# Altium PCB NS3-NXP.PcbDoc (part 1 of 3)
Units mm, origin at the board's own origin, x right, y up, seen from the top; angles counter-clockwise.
Board outline 147 x 83 mm, 2 copper layers (Top Layer, Bottom Layer); 303 components, 312 nets, 1163 pads, 118 vias.
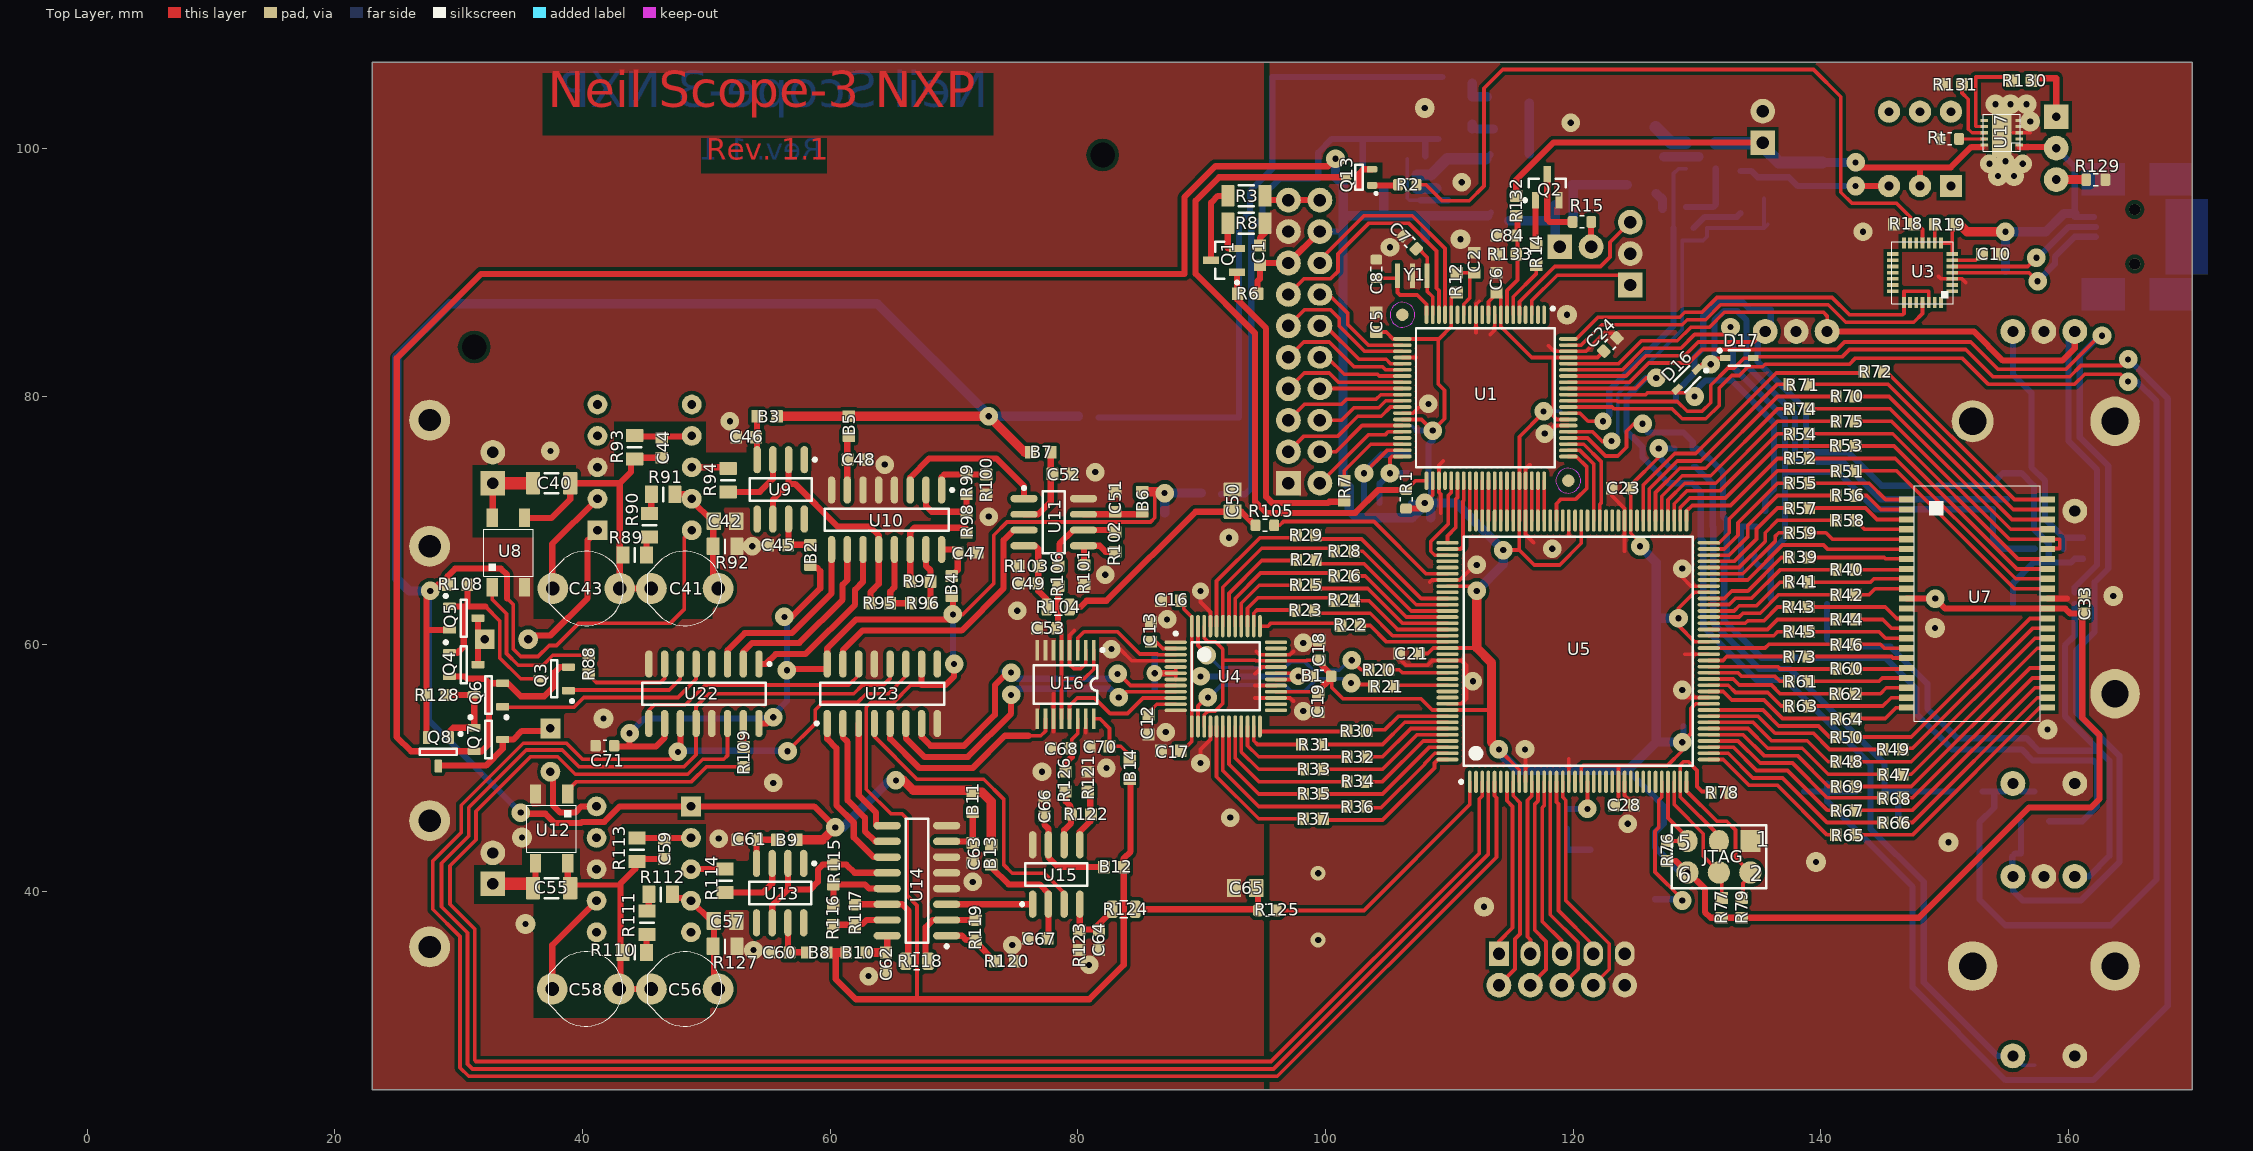
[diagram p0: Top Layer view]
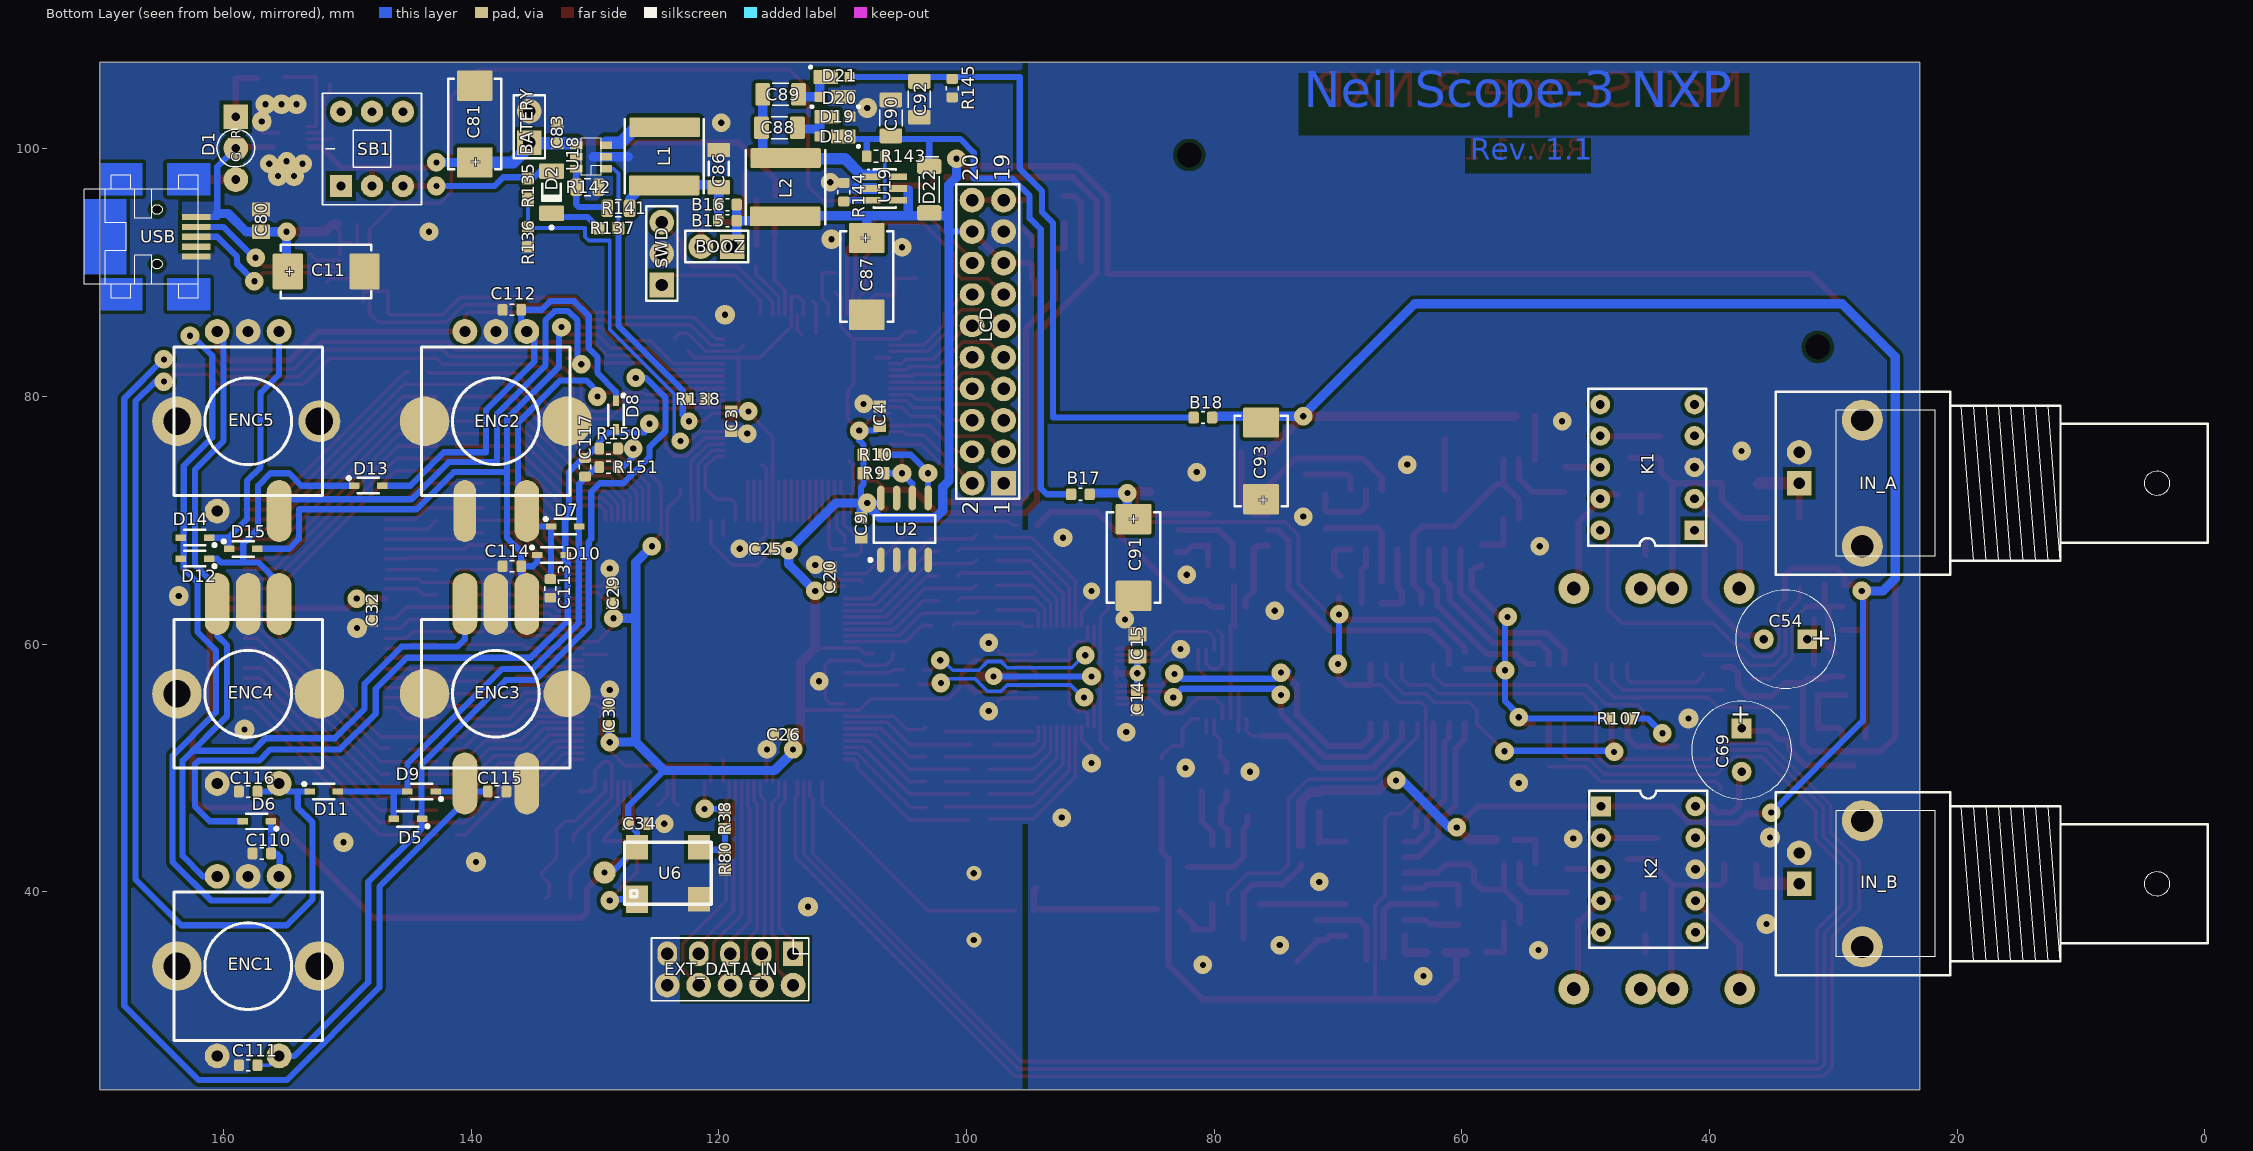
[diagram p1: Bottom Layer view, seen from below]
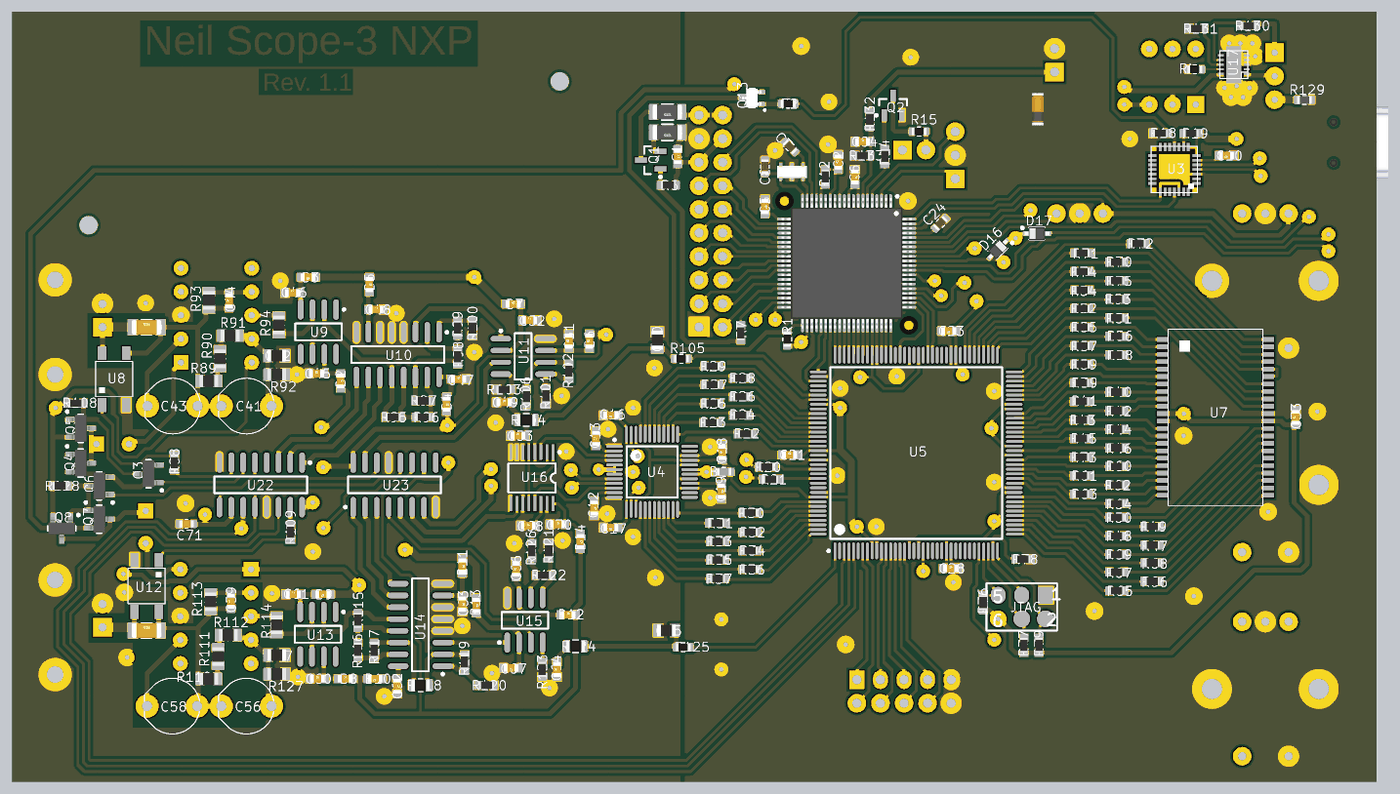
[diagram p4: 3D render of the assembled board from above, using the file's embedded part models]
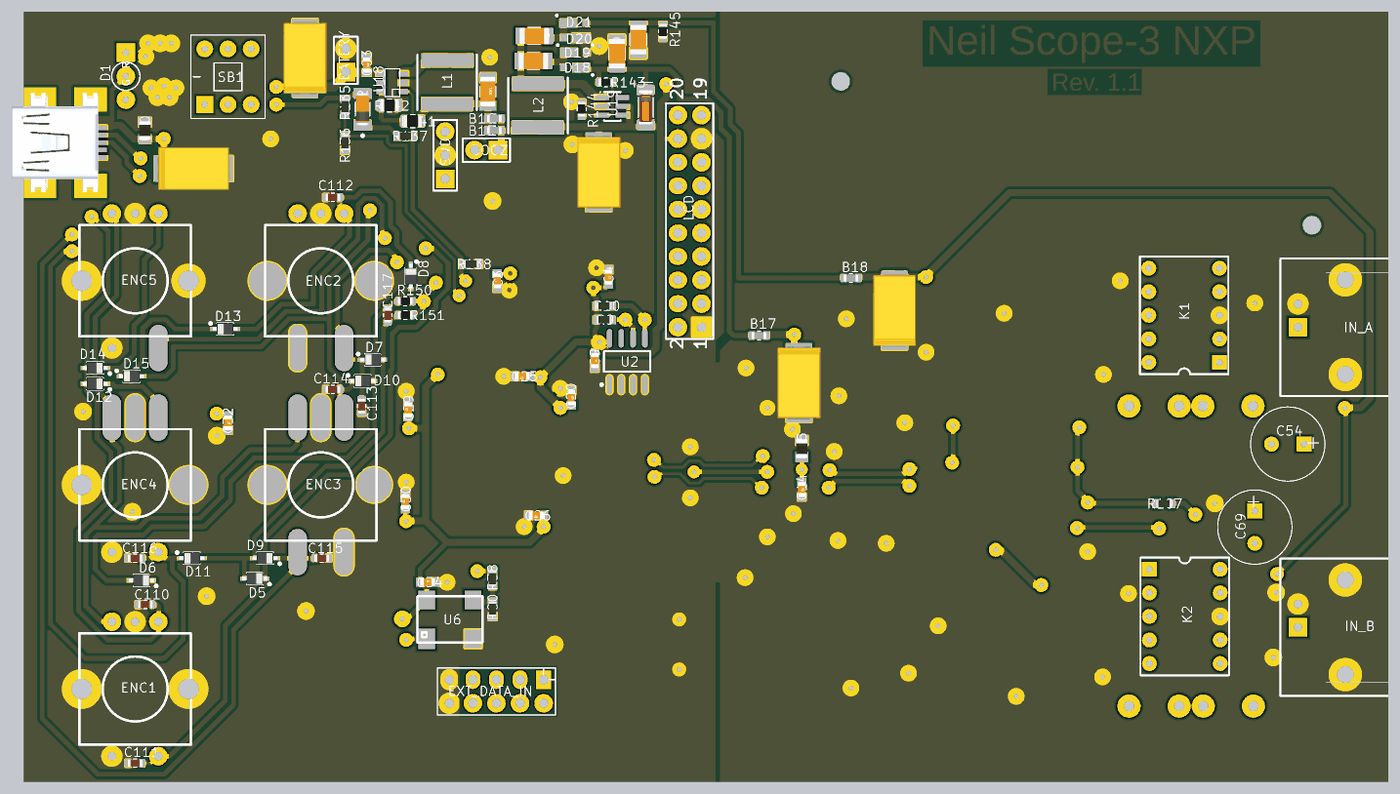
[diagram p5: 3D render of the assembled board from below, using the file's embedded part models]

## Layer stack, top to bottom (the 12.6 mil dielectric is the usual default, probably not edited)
Top Layer: signal copper 0.0356
Dielectric: dielectric 0.32, FR-4, Dk 4.8
Bottom Layer: signal copper 0.0356

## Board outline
23,24 170,24 170,107 23,107

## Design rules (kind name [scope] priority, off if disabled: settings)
Clearance Clearance_2 [InNet('AGND') vs InNet('DGND')] p1: gap=0
Clearance Clearance_1 [(IsPad OR IsTrack) vs (IsPad OR IsTrack)] p2: gap=0.19
Clearance [All] p3: gap=0.3
ComponentClearance [All] p1 off: gap=0.254 collisioncheckmode=3 verticalgap=0.254 showdistances=FALSE
MinimumSolderMaskSliver [All] p1 off: minsoldermaskwidth=0.254
PasteMaskExpansion [All] p1 off: expansion=0
PlaneClearance [All] p1: clearance=0.4
PlaneConnect [All] p1: planeconnectstyle=Relief reliefexpansion=0.508 reliefentries=4 reliefconductorwidth=0.4 reliefairgap=0.4
PolygonConnect [All] p1: connectstyle=Relief reliefconductorwidth=0.5 reliefentries=4 polygonreliefangle="90 Angle" airgapwidth=-0.1
RoutingVias [All] p1: holewidth=0.5 width=1.5 viastyle="Through Hole" minholewidth=0.5 minwidth=1 maxholewidth=0.6 maxwidth=2
ShortCircuit ShortCircuit_1 [InNet('AGND') vs InNet('DGND')] p1: allowed=TRUE
ShortCircuit [All] p2: allowed=FALSE
SilkToSilkClearance [All] p1 off: silktosilkclearance=0.254
SilkscreenOverComponentPads [IsPad] p1 off: minsilkscreentomaskgap=0.254
SolderMaskExpansion [All] p1 off: expansion=0.15
Width [All] p1: maxlimit=2 minlimit=0.25 preferedwidth=0.3
20 further rules are at their usual default settings.

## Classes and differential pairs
component class U_Analog: B2 B3 B4 B5 B6 B7 B8 B9 B10 B11 B12 B13 B14 C40 C41 C42 C43 C44 C45 C46 C47 C48 C49 C50 C51 C52 C53 C54 C55 C56 C57 C58 C59 C60 C61 C62 C63 C64 C65 C66 C67 C68 C69 C70 C71 IN_A IN_B K1 K2 Q3 Q4 Q5 Q6 Q7 Q8 R88 R89 R90 R91 R92 R93 R94 R95 R96 R97 R98 R99 R100 R101 R102 R103 R104 R105 R106 R107 R108 R109 R110 R111 R112 R113 R114 R115 R116 R117 R118 R119 R120 R121 R122 R123 R124 R125 R126 R127 R128 U8 U9 U10 U11 U12 U13 U14 U15 U16 U22 U23
net class ENCBUT[3..0]: ENCBUT0 ENCBUT1 ENCBUT2 ENCBUT3
net class ENCA[2..0]: ENCA0 ENCA1 ENCA2
net class Q[7..0]: Q0 Q1 Q2 Q3 Q4 Q5 Q6 Q7

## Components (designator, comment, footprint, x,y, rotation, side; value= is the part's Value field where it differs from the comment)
B1 "BEAD" BEAD0603 99.7,57.4 r0 top
B2 "BEAD" C0603NH080 58.4,67.2 r270 top
B3 "BEAD" C0603NH080 54.9,78.4 r180 top
B4 "BEAD" C0603NH080 69.8,64.7 r270 top
B5 "BEAD" C0603NH080 61.5,77.6 r270 top
B6 "BEAD" C0603NH080 85.2,71.5 r90 top
B7 "BEAD" C0603NH080 77,75.5 r0 top
B8 "BEAD" C0603NH080 58.9,35.1 r0 top
B9 "BEAD" C0603NH080 56.5,44.2 r180 top
B10 "BEAD" C0603NH080 62.1,35.1 r180 top
B11 "BEAD" C0603NH080 71.5,47.25 r270 top
B12 "BEAD" C0603NH080 82.9,42 r0 top
B13 "BEAD" C0603NH080 73,43 r270 top
B14 "BEAD" C0603NH080 84.2,49.9 r270 top
B15 "BEAD" BEAD0603 119.3,94.2 r180 bottom
B16 "BEAD" BEAD0603 119.3,95.5 r180 bottom
B17 "BEAD" BEAD0603 90.8,72.1 r180 bottom
B18 "BEAD" BEAD0603 80.9,78.3 r180 bottom
BATERY "Header 2" HDR1X2 135.3,100.5 r90 bottom
BOOZ "Header 2" HDR1X2 118.9,92.1 r0 bottom
C1 "Cap" C0603NH080 94.7,91.4 r270 top
C2 "Cap" C0603NH080 112,90.8 r90 top
C3 "Cap" C0603NH080 119,78 r90 bottom
C4 "Cap" C0603NH080 107,78.4 r270 bottom
C5 "Cap" C0603NH080 104.1,86 r270 top
C6 "Cap" C0603NH080 113.8,89.2 r270 top
C7 "Cap" C0603_Samsung 106.8,92.45 r315 top
C8 "Cap" C0603_Samsung 104.1,90.3 r270 top
C9 "Cap" C0603NH080 108.5,69.4 r270 bottom
C10 "Cap" C0603NH080 153.8,91.5 r180 top
C11 "ECap" CAPMP7343X280N 151.7,90.1 r180 bottom
C12 "Cap" C0603NH080 85.7,53.5 r270 top
C13 "Cap" C0603NH080 85.9,61 r90 top
C14 "Cap" C0603NH080 86.2,55.5 r270 bottom
C15 "Cap" C0805NH145 86.2,59.9 r270 bottom
C16 "Cap" C0603NH080 87.5,63.5 r180 top
C17 "Cap" C0603NH080 87.5,51.4 r180 top
C18 "Cap" C0603NH080 99.5,59.5 r90 top
C19 "Cap" C0603NH080 99.4,55.3 r270 top
C20 "Cap" C0603NH080 111,65.4 r270 bottom
C21 "Cap" C0603NH080 106.75,59.25 r0 top
C23 "Cap" C0603NH080 123.9,72.6 r180 top
C24 "Cap" C0603_Samsung 123,84.2 r45 top
C25 "Cap" C0603NH080 116.3,67.7 r0 bottom
C26 "Cap" C0603NH080 114.8,52.7 r0 bottom
C28 "Cap" C0603NH080 124.1,47 r0 top
C29 "Cap" C0603NH080 128.6,64.1 r90 bottom
C30 "Cap" C0603NH080 128.9,54.2 r90 bottom
C32 "Cap" C0603NH080 148,62.7 r270 bottom
C33 "Cap" C0603NH080 161.252,63.276 r90 top
C34 "Cap" C0603NH080 126.5,45.5 r180 bottom
C40 "Cap" C1206NH190 37.5,73 r0 top
C41 "Cap_Var" Cap_Var 48.25,64.5 r180 top
C42 "Cap" C0805NH145 51.501,69.926 r180 top
C43 "Cap_Var" Cap_Var 40.3,64.5 r180 top
C44 "NPO" C0603NH080 46.4,75.85 r90 top
C45 "Cap" C0603NH080 55.8,68 r0 top
C46 "Cap" C0603NH080 53.2,76.7 r0 top
C47 "Cap" C0603NH080 71.1,67.4 r0 top
C48 "Cap" C0603NH080 62.2,74.9 r0 top
C49 "Cap" C0603NH080 76,64.9 r0 top
C50 "Cap" C0805NH145 92.5,71.6 r270 top
C51 "Cap" C0603NH080 83,71.5 r90 top
C52 "Cap" C0603NH080 78.75,73.75 r0 top
C53 "NPO" C0603NH080 77.5,61.3 r0 top
C54 "CE_Al" CE_D8_3.5 32.1,60.4 r0 bottom
C55 "Cap" C1206NH190 37.5,40.3 r0 top
C56 "Cap_Var" Cap_Var 48.25,32.15 r180 top
C57 "Cap" C0805NH145 51.5,37.65 r180 top
C58 "Cap_Var" Cap_Var 40.25,32.15 r180 top
C59 "NPO" C0603NH080 46.6,43.45 r90 top
C60 "Cap" C0603NH080 55.9,35.1 r0 top
C61 "Cap" C0603NH080 53.3,44.2 r0 top
C62 "Cap" C0603NH080 64.5,34.3 r270 top
C63 "Cap" C0603NH080 71.5,43.15 r270 top
C64 "Cap" C0603NH080 81.7,36.1 r90 top
C65 "Cap" C0805NH145 93.5,40.3 r0 top
C66 "Cap" C0603NH080 77.3,46.9 r90 top
C67 "Cap" C0603NH080 76.75,36.25 r180 top
C68 "NPO" C0603NH080 78.6,51.6 r0 top
C69 "CE_Al" CE_D8_3.5 37.4,53.2 r270 bottom
C70 "Cap" C0603NH080 81.75,51.75 r0 top
C71 "Cap" C0603_Murata 41.8,51.8 r0 top
C80 "Cap" C0805NH145 156.95,94.2 r270 bottom
C81 "ECap" CAPMP7343X280N 139.7,102 r90 bottom
C83 "Cap" C0603NH080 133.05,101.25 r270 bottom
C84 "Cap" C0603NH080 114.6,93 r0 top
C86 "Cap" C1206NH190 120,98.4 r270 bottom
C87 "ECap" CAPMP7343X280N 108.05,89.7 r270 bottom
C88 "Cap" C1206_Murata 115.1,101.7 r180 bottom
C89 "Cap" C1206_Murata 115,104.4 r180 bottom
C90 "Cap" C1206_Murata 106.1,102.5 r270 bottom
C91 "ECap" CAPMP7343X280N 86.5,67 r270 bottom
C92 "Cap" C1206_Murata 103.8,104 r270 bottom
C93 "ECap" CAPMP7343X280N 76.2,74.8 r90 bottom
C110 "Cap" C0603_Samsung 156.9,43.1 r180 bottom
C111 "Cap" C0603_Samsung 158,26 r180 bottom
C112 "Cap" C0603_Samsung 136.7,87 r180 bottom
C113 "Cap" C0603_Samsung 133.6,64.5 r270 bottom
C114 "Cap" C0603_Samsung 136.7,66.3 r180 bottom
C115 "Cap" C0603_Samsung 137.9,48.1 r180 bottom
C116 "Cap" C0603_Samsung 158,48.1 r0 bottom
C117 "Cap" C0603_Samsung 130.8,74.3 r90 bottom
D1 "LightDiode" D_C_LightDiode_3pin_D3 159,102.6 r270 bottom
D2 "Diode" SOD80_VISHAY_MINIMELF#1 133.5,96.5 r90 bottom
D5 "D_Schottky" SOD323FL_NXP 145.1,45.9 r0 bottom
D6 "D_Schottky" SOD323FL_NXP 157.3,45.7 r0 bottom
D7 "D_Schottky" SOD323FL_NXP 132.4,69.5 r180 bottom
D8 "D_Schottky" SOD323FL_NXP 128.3,78.5 r270 bottom
D9 "D_Schottky" SOD323FL_NXP 144,48.1 r0 bottom
D10 "D_Schottky" SOD323FL_NXP 133.5,67.2 r180 bottom
D11 "D_Schottky" SOD323FL_NXP 151.9,48.1 r180 bottom
D12 "D_Schottky" SOD323FL_NXP 162.3,66.9 r0 bottom
D13 "D_Schottky" SOD323FL_NXP 148.3,72.8 r180 bottom
D14 "D_Schottky" SOD323FL_NXP 162.3,68.6 r0 bottom
D15 "D_Schottky" SOD323FL_NXP 158.4,67.7 r180 bottom
D16 "D_Schottky" SOD323FL_NXP 129.2,81.4 r225 top
D17 "D_Schottky" SOD323FL_NXP 133.4,83.1 r0 top
D18 "D_Schottky" SOD323FL_VISHAY_MICROSMP 110.6,101 r0 bottom
D19 "D_Schottky" SOD323FL_VISHAY_MICROSMP 110.6,102.6 r180 bottom
D20 "D_Schottky" SOD323FL_VISHAY_MICROSMP 110.6,104.2 r0 bottom
D21 "D_Schottky" SOD323FL_VISHAY_MICROSMP 110.7,105.8 r180 bottom
D22 "Diode" SOD80_VISHAY_MINIMELF#2 103,96.7 r270 bottom
ENC1 "Encoder" Encoder#1 158,34 r270 bottom
ENC2 "Encoder" Encoder#2 138,78 r270 bottom locked
ENC3 "Encoder" Encoder#3 138,56 r270 bottom locked
ENC4 "Encoder" Encoder#4 158,56 r270 bottom locked
ENC5 "Encoder" Encoder#5 158,78 r270 bottom locked
EXT_DATA_IN "BH-10" BH-10 114,35 r0 bottom locked
IN_A "BNC" "BNC_RA CON" 32.75,73 r0 bottom locked
IN_B "BNC" "BNC_RA CON" 32.75,40.65 r0 bottom locked
JTAG "Header 3X2" HDR2X3 134.3,44.1 r180 top
K1 "AxW-K-x" DIP10_Relay 41.2,69.2 r0 bottom
K2 "AxW-K-x" DIP10_Relay 48.75,46.9 r180 bottom
L1 "L" L2424_TAIYO_NR60XX 124.4,99.4 r270 bottom
L2 "L" L2424_TAIYO_NR60XX 114.6,96.9 r90 bottom
LCD "Header 10X2" HDR2X10 97,73 r90 bottom
Q1 "BC847" SOT23_N 91.8,91 r180 top
Q2 "IRLML2402" SOT23_N 117.9,96.9 r90 top
Q3 "IRLML6302" SOT23-3_DISCRETE 37.7,57.2 r180 top
Q4 "IRLML6302" SOT23-3_DISCRETE 30.4,58.35 r0 top
Q5 "IRLML2402" SOT23-3_DISCRETE 30.4,62.1 r0 top
Q6 "IRLML6302" SOT23-3_DISCRETE 32.4,55.9 r180 top
Q7 "IRLML6302" SOT23-3_DISCRETE 32.4,52.3 r0 top
Q8 "IRLML2402" SOT23-3_DISCRETE 28.35,51.3 r270 top
Q13 "NPN" SOT323 102.7,97.7 r180 top
R1 "R" R0603_UniOhm 106.5,71.7 r270 top
R2 "R" R0603_UniOhm 106.6,97.1 r0 top
R3 "R" R1206NH084 93.6,96.2 r180 top
R6 "R" R0603N 93.7,88.3 r0 top
R7 "R" R0603N 101.5,72.4 r90 top
R8 "R" R1206NH084 93.6,94 r180 top
R9 "R" R0603N 107.5,73.8 r0 bottom
R10 "R" R0603N 107.5,75.3 r0 bottom
R12 "R" R0603N 110.6,89.2 r270 top
R14 "R" R0603N 117,91.4 r90 top
R15 "R" R0603_UniOhm 120.7,94.1 r0 top
R18 "R" R0603N 146.7,93.9 r0 top
R19 "R" R0603N 150,93.9 r180 top
R20 "R" R0603N 104.274,57.942 r180 top
R21 "R" R0603N 104.706,56.592 r180 top
R22 "R" R0603N 102,61.5 r0 top
R23 "R" R0603N 98.3,62.7 r0 top
R24 "R" R0603N 101.5,63.5 r0 top
R25 "R" R0603N 98.4,64.8 r0 top
R26 "R" R0603N 101.5,65.5 r0 top
R27 "R" R0603N 98.4,66.8 r0 top
R28 "R" R0603N 101.5,67.5 r0 top
R29 "R" R0603N 98.4,68.8 r0 top
R30 "R" R0603N 102.5,53 r0 top
R31 "R" R0603N 98.9,51.9 r0 top
R32 "R" R0603N 102.5,50.9 r0 top
R33 "R" R0603N 99,49.9 r0 top
R34 "R" R0603N 102.5,48.9 r0 top
R35 "R" R0603N 99,47.9 r0 top
R36 "R" R0603N 102.5,46.9 r0 top
R37 "R" R0603N 99,45.9 r0 top
R38 "R" R0603N 119.5,45.9 r90 bottom
R39 "R" R0603N 138.2,67 r0 top
R40 "R" R0603N 142,66 r0 top
R41 "R" R0603N 138.2,65 r0 top
R42 "R" R0603N 142,64 r0 top
R43 "R" R0603N 138.2,63 r0 top
R44 "R" R0603N 142,62 r0 top
R45 "R" R0603N 138.2,61 r0 top
R46 "R" R0603N 142,60 r0 top
R47 "R" R0603N 145.8,49.5 r0 top
R48 "R" R0603N 142,50.5 r0 top
R49 "R" R0603N 145.8,51.5 r0 top
R50 "R" R0603N 142,52.5 r0 top
R51 "R" R0603N 142,74 r0 top
R52 "R" R0603N 138.25,75 r0 top
R53 "R" R0603N 142,76 r0 top
R54 "R" R0603N 138.25,77 r0 top
R55 "R" R0603N 138.25,73 r180 top
R56 "R" R0603N 142,72 r180 top
R57 "R" R0603N 138.25,71 r180 top
R58 "R" R0603N 142,70 r180 top
R59 "R" R0603N 138.25,69 r180 top
R60 "R" R0603N 142,58 r180 top
R61 "R" R0603N 138.2,57 r180 top
R62 "R" R0603N 142,56 r180 top
R63 "R" R0603N 138.2,55 r180 top
R64 "R" R0603N 142,54 r180 top
R65 "R" R0603N 142,44.6 r180 top
R66 "R" R0603N 145.8,45.6 r180 top
R67 "R" R0603N 142,46.6 r180 top
R68 "R" R0603N 145.8,47.6 r180 top
R69 "R" R0603N 142,48.5 r180 top
R70 "R" R0603N 142,80 r180 top
R71 "R" R0603N 138.25,81 r180 top
R72 "R" R0603N 144.3,82 r180 top
R73 "R" R0603N 138.2,59 r180 top
R74 "R" R0603N 138.25,79 r180 top
R75 "R" R0603N 142,78 r180 top
R76 "R" R0603N 127.6,43.3 r90 top
R77 "R" R0603N 132,38.7 r90 top
R78 "R" R0603N 131.9,48 r180 top
R79 "R" R0603N 133.6,38.7 r90 top
R80 "R" R0603N 119.5,42.6 r270 bottom
R88 "R" R0603N 40.5,58.4 r90 top
R89 "R" R0805NH070 44.2,67.2 r180 top
R90 "R" R0805NH070 45.4,69.6 r270 top
R91 "R" R0805NH070 46.5,72.1 r180 top
R92 "R" R0805NH070 51.5,67.9 r180 top
R93 "R" R0805NH070 44.2,75.9 r90 top
R94 "R" R0805NH070 51.75,73.25 r270 top
R95 "R" R0603N 64.05,63.3 r180 top
R96 "R" R0603N 67.3,63.3 r180 top
R97 "R" R0603N 67.3,65.05 r0 top
R98 "R" R0603N 71,69.8 r270 top
R99 "R" R0603N 71,72.9 r270 top
R100 "R" R0603N 72.6,72.9 r90 top
R101 "R" R0603N 80.5,65.6 r90 top
R102 "R" R0603N 83,68.25 r90 top
R103 "R" R0603N 76,66.3 r0 top
R104 "R" R0805_YAGEO 78.4,63 r0 top
R105 "R" R0603_UniOhm 95.1,69.6 r0 top
R106 "R" R0603N 78.4,65.5 r270 top
R107 "R" R0603N 47.2,54 r0 bottom
R108 "R" R0603N 29.9,64.8 r0 top
R109 "R" R0603N 53,50.9 r270 top
R110 "R" R0805NH070 44.2,35.1 r180 top
R111 "R" R0805NH070 45.2,37.5 r270 top
R112 "R" R0805NH070 46.3,39.8 r180 top
R113 "R" R0805NH070 44.4,43.4 r90 top
R114 "R" R0805NH070 51.5,40.9 r270 top
R115 "R" R0603N 60.25,41.4 r90 top
R116 "R" R0603N 60.25,38.15 r90 top
R117 "R" R0603N 62,38.15 r270 top
R118 "R" R0805_UniOhm 67,34.4 r180 top
R119 "R" R0603N 71.75,36.9 r90 top
R120 "R" R0603N 74.1,34.4 r180 top
R121 "R" R0603N 80.8,48.9 r270 top
R122 "R" R0603N 80.25,46.25 r180 top
R123 "R" R0603N 80.1,36.1 r90 top
R124 "R" R0805_YAGEO 83.7,38.6 r0 top
R125 "R" R0603_UniOhm 95.3,38.5 r0 top
R126 "R" R0603N 79,48.9 r90 top
R127 "R" R0805NH070 51.5,35.6 r180 top
R128 "R" R0603N 28.2,55.9 r0 top
R129 "R" R0603_Pan_ERJ3 162.2,97.5 r180 top
R130 "R" R0603N 156.2,105.5 r0 top
R131 "R" R0603N 150.6,105.2 r0 top
R132 "R" R0603N 115.4,95.4 r90 top
R133 "R" R0603N 114.6,91.5 r0 top
R135 "R" R0603N 135.4,96.8 r90 bottom
R136 "R" R0603N 135.4,92.9 r270 bottom
R137 "R" R0603N 128.9,93.6 r180 bottom
R138 "R" R0603N 121.8,79.8 r180 bottom
R141 "R" R0805_UniOhm 128.1,95.2 r180 bottom
R142 "R" R0805_UniOhm 130.6,96.9 r0 bottom
R143 "R" R0603_UniOhm 107.3,99.4 r0 bottom
R144 "R" R0603_UniOhm 109.9,96.5 r270 bottom
R145 "R" R0603_UniOhm 101.15,104.9 r270 bottom
R150 "R" R0603_UniOhm 128.9,75.8 r180 bottom
R151 "R" R0603_UniOhm 128.9,74.3 r180 bottom
Rt "R" R0603_UniOhm 150.4,100.8 r0 top
SB1 "SB_8x8" SB_8x8 148,100 r180 bottom locked
SWD "Header 3" HDR1X3 124.6,89 r90 bottom
U1 "LPC1758FBD80" PQFP80 112.9,79.9 r270 top
U2 "FM24CL64" SOP8_N 105,69.3 r90 bottom
U3 "CP2102" QFN-28 148.2,90 r180 top
U4 "AD9288" TQFP48_N 91.948,57.404 r0 top
U5 "EPM570T144C5N" TQFP144_N 120.396,59.436 r90 top locked
U6 "KXO-V97 100MHz" KXO-V97 126.6,39.4 r180 bottom
U7 "CY7C1041" TSOP-44-II 152.616,63.276 r270 top
U8 "CPC1035N" SOIC-4N 34,67.4 r0 top
U9 "AD8065" SO8_N#1 56,72.5 r270 top
U10 "74HC4051D" 751B-05_N 64.55,70.05 r270 top
U11 "AD8129" SO8_N#2 78.05,69.85 r0 top
U12 "CPC1035N" SOIC-4N 37.5,45.1 r180 top
U13 "AD8065" SO8_N#1 55.95,39.9 r270 top
U14 "74HC4051D" 751B-05_N 67,40.9 r180 top
U15 "AD8129" SO8_N#1 78.25,41.4 r90 top
U16 "74HC4052" TSSOP16A 79,56.75 r180 top
U17 "LM3658" WSON10 154.6,101.3 r90 top
U18 "SY8009B" SOT-23-6 129.1,98.4 r90 bottom
U19 "MT3608 (SDB628x)" 1262-01 106.6,96.8 r270 bottom
U22 "74HC595M" SO16_N#1 49.8,56 r270 top
U23 "74HC595M" SO16_N#2 64.2,56 r90 top
USB "USB MiniB" "USB miniB (SMD NNM)" 162.2,94.5 r180 bottom locked
Y1 "XTAL_CAP" CSTCE_G 107,89.75 r270 top

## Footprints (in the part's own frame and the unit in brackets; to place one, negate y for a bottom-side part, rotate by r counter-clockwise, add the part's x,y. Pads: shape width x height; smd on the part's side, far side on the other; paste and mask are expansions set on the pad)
751B-05_N [mm] "SOIC, 16-Leads, Body 9.9x3.9mm, Pitch 1.27mm, IPC Medium Density"
  oval 2.2x0.6 smd: 1(-2.4,4.445) 2(-2.4,3.175) 3(-2.4,1.905) 4(-2.4,0.635) 5(-2.4,-0.635) 6(-2.4,-1.905) 7(-2.4,-3.175) 8(-2.4,-4.445) 9(2.4,-4.445) 10(2.4,-3.175) 11(2.4,-1.905) 12(2.4,-0.635) 13(2.4,0.635) 14(2.4,1.905) 15(2.4,3.175) 16(2.4,4.445)
  silkscreen extent -2.52,-5 0.9,5.42, body extent -1.95,-4.95 1.95,4.95, height 1.75
1262-01 [mm] "SOT-457/SC-74; 6 Leads; Body 3 x 3 mm, inc. leads (LxW max)"
  rect 0.55x1.45 smd: 1(-0.95,-1.075) 2(0,-1.075) 3(0.95,-1.075) 4(0.95,1.075) 5(0,1.075) 6(-0.95,1.075)
  silkscreen extent -1.57,-1.35 1.55,0.9
BEAD0603 [mm] "Ferrite Bead, Chip; 1.60 mm L X 0.80 mm W X 0.95 mm H body"
  rrect40% 0.85x0.95 smd paste-0.025 mask+0.05: 1(-0.75,0) 2(0.75,0)
  silkscreen extent -0.15,-0.48 0.15,0.48, body extent -0.8,-0.4 0.8,0.4, height 0.95
BH-10 [mm] "Connector 2x5 2.54mm (100inch)"
  rect 1.6x2 hole 1: 1(0,0)
  round 2 hole 1: 2(0,2.54) 4(2.54,2.54) 6(5.08,2.54) 8(7.62,2.54) 10(10.16,2.54)
  oval 1.6x2 hole 1: 3(2.54,0) 5(5.08,0) 7(7.62,0) 9(10.16,0)
  silkscreen extent -1.27,-1.27 11.43,3.81
"BNC_RA CON" [mm] "Connector; BNC Elbow"
  rect 2x2 hole 0.9: 1(0,0)
  round 3.3 hole 1.8: 2(-5.1,-5.1) 2(-5.1,5.1)
  round 2 hole 0.9: 2(0,-2.5)
  silkscreen extent -33,-7.4 1.9,7.4
C0603_Murata [mm] "Capacitor, Chip; 1.60 mm L X 0.80 mm W X 0.90 mm H body"
  rrect40% 0.85x0.95 smd paste-0.025 mask+0.05: 1(-0.75,0) 2(0.75,0)
  silkscreen extent -0.15,-0.45 0.15,0.45, body extent -0.8,-0.4 0.8,0.4, height 0.9
C0603_Samsung [mm] "Capacitor, Chip; 1.60 mm L X 0.80 mm W X 0.90 mm H body"
  rrect40% 0.8x0.95 smd paste-0.025 mask+0.05: 1(-0.75,0) 2(0.75,0)
  silkscreen extent -0.17,-0.45 0.17,0.45, body extent -0.8,-0.4 0.8,0.4, height 0.9
C0603NH080 [mm] "Capacitor,Chip;1.60mm L X 0.80mm W X 0.90mm H"
  rrect10% 0.95x1 smd paste-0.025 mask+0.05: 1(-0.8,0) 2(0.8,0)
  body extent -0.8,-0.4 0.8,0.4, height 0.3
C0805NH145 [mm] "Capacitor,Chip;2.00mm L X 1.25mm W X 1.45mm H"
  rrect10% 1.15x1.45 smd paste-0.025 mask+0.05: 1(-0.9,0) 2(0.9,0)
  body extent -1,-0.62 1,0.63, height 0.6
C1206_Murata [mm] "Capacitor, Chip; 3.20 mm L X 1.60 mm W X 1.80 mm H body"
  rrect20% 1.2x1.8 smd: 1(-1.45,0) 2(1.45,0)
  silkscreen extent -0.67,-0.9 0.67,0.9, body extent -1.6,-0.9 1.6,0.9, height 1.6
C1206NH190 [mm] "Capacitor, Chip; 3.20mm L X 1.60mm W X 1.90mm H"
  rrect10% 1.15x1.8 smd paste-0.025 mask+0.05: 1(-1.5,0) 2(1.5,0)
  silkscreen extent -0.55,-0.8 0.55,0.8, body extent -1.6,-0.8 1.6,0.8, height 1
Cap_Var [mm]
  round 2.5 hole 1.1: 1(-2.7,0) 2(2.7,0)
  silkscreen extent -3,-3 3,3
CAPMP7343X280N [mm] "Capacitor,polarized,Molded Body;7.30mm L X 4.30mm W X 2.80mm H"
  rrect10% 2.45x2.9 smd paste-0.025 mask+0.05: A(-3.1,0) C(3.1,0)
  silkscreen extent -3.65,-2.15 3.65,2.15, body extent -3.93,-2.31 3.93,2.31, height 3.1
CE_D8_3.5 [mm] "Electrolytic Capacitor, Diametr 8mm, Pin-Pin 3.5mm"
  rect 1.6x1.6 hole 0.7: 1(0,0)
  round 1.6 hole 0.7: 2(3.5,0)
  silkscreen extent -2.25,-4 5.75,4
CSTCE_G [mm]
  rrect15% 2x0.4 smd paste-0.025 mask+0.05: 1(0,1.2) 2(0,0) 3(0,-1.2)
  body extent -0.65,-1.6 0.65,1.6, height 0.7
D_C_LightDiode_3pin_D3 [mm] "Dual Color Light Diode 3pin Diametr=3mm"
  rect 2x2 hole 0.7: 1(0,0)
  round 2 hole 0.7: 2(2.54,0) 3(5.08,0)
  silkscreen extent 1.02,-1.52 4.06,1.52
DIP10_Relay [mm]
  rect 1.6x1.6 hole 0.7: 1(0,0)
  round 1.6 hole 0.7: 2(0,-2.54) 3(0,-5.08) 4(0,-7.62) 5(0,-10.16) 6(7.62,-10.16) 7(7.62,-7.62) 8(7.62,-5.08) 9(7.62,-2.54) 10(7.62,0)
  silkscreen extent -0.96,-11.43 8.58,1.27, body extent -0.96,-11.43 8.58,1.27, height 10
Encoder#1 [mm]
  round 4 hole 2.2: 0(0,-5.75) 0(0,5.75)
  round 2 hole 0.9: 1(-7.25,2.5) 2(-7.25,0) 3(-7.25,-2.5) 4(7.25,2.5) 5(7.25,-2.5)
  silkscreen extent -6,-6 6,6
Encoder#2 [mm]
  round 4 smd: 0(0,-5.75) 0(0,5.75)
  round 2 hole 0.9: 1(-7.25,2.5) 2(-7.25,0) 3(-7.25,-2.5)
  oval 5x2 smd: 4(7.25,2.5)
  oval 5x1.8 smd: 5(7.25,-2.5)
  silkscreen extent -6,-6 6,6
Encoder#3 [mm]
  round 4 smd: 0(0,-5.75)
  round 3.8 smd: 0(0,5.75)
  oval 5x2 smd: 1(-7.25,2.5) 2(-7.25,0) 3(-7.25,-2.5) 4(7.25,2.5) 5(7.25,-2.5)
  silkscreen extent -6,-6 6,6
Encoder#4 [mm]
  round 4 hole 2.2: 0(0,-5.75)
  round 4 smd: 0(0,5.75)
  oval 5x2 smd: 1(-7.25,2.5) 2(-7.25,0) 3(-7.25,-2.5)
  round 2 hole 0.9: 4(7.25,2.5) 5(7.25,-2.5)
  silkscreen extent -6,-6 6,6
Encoder#5 [mm]
  round 4 hole 2.2: 0(0,-5.75)
  round 3.4 hole 2.2: 0(0,5.75)
  round 2 hole 0.9: 1(-7.25,2.5) 2(-7.25,0) 3(-7.25,-2.5) 5(7.25,-2.5)
  oval 5x2 smd: 4(7.25,2.5)
  silkscreen extent -6,-6 6,6
HDR1X2 [mm] "Connector; Header; 2 Position"
  rect 2x2 hole 1: 1(0,0)
  round 2 hole 1: 2(2.54,0)
  silkscreen extent -1.27,-1.27 3.81,1.27
HDR1X3 [mm] "Connector; Header; 3 Position"
  rect 2x2 hole 1: 1(0,0)
  round 2 hole 1: 2(2.54,0) 3(5.08,0)
  silkscreen extent -1.27,-1.27 6.35,1.27
HDR2X3 [mm] "Connector; Header; 3x2 Position"
  rect 1.6x1.8 smd: 1(0,0)
  round 1.8 smd: 2(0,2.54) 4(2.54,2.54)
  oval 1.6x1.8 smd: 3(2.54,0) 5(5.08,0)
  round 1.8 hole 0.5: 6(5.08,2.54)
  silkscreen extent -1.27,-1.27 6.35,3.81
HDR2X10 [mm] "Connector; Header; 10x2 Position"
  rect 2x2 hole 1: 1(0,0)
  round 2 hole 1: 2(0,2.54) 3(2.54,0) 5(5.08,0) 7(7.62,0) 9(10.16,0) 11(12.7,0) 13(15.24,0) 15(17.78,0) 17(20.32,0) 18(20.32,2.54) 19(22.86,0) 20(22.86,2.54)
  oval 1.8x2 hole 1: 4(2.54,2.54) 6(5.08,2.54) 8(7.62,2.54) 10(10.16,2.54) 12(12.7,2.54) 14(15.24,2.54) 16(17.78,2.54)
  silkscreen extent -1.27,-1.27 24.13,3.81
KXO-V97 [mm]
  rect 1.8x2.2 smd: 1(0,0)
  rect 1.8x2 smd: 2(5,0) 3(5,4.2) 4(0,4.2)
  silkscreen extent -1,-0.4 6,4.6
L2424_TAIYO_NR60XX [mm]
  rrect15% 1.6x5.7 smd paste-0.05 mask+0.05: 1(-2.35,0.045) 2(2.35,0)
  silkscreen extent -3,-3.2 3,3.2, body extent -3.1,-3.1 3.1,3.1, height 2.8
PQFP80 [mm] "QFP,0.50mm pitch,square;16 pin X 16 pin,10.00mm X 10.00mm X 1.60mm H body"
  oval 1.5x0.3 smd mask+0.05: 1(-6.7,4.75) 2(-6.7,4.25) 3(-6.7,3.75) 4(-6.7,3.25) 5(-6.7,2.75) 6(-6.7,2.25) 7(-6.7,1.75) 8(-6.7,1.25) 9(-6.7,0.75) 10(-6.7,0.25) 11(-6.7,-0.25) 12(-6.7,-0.75) 13(-6.7,-1.25) 14(-6.7,-1.75) 15(-6.7,-2.25) 16(-6.7,-2.75) 17(-6.7,-3.25) 18(-6.7,-3.75) 19(-6.7,-4.25) 20(-6.7,-4.75) 41(6.7,-4.75) 42(6.7,-4.25) 43(6.7,-3.75) 44(6.7,-3.25) 45(6.7,-2.75) 46(6.7,-2.25) 47(6.7,-1.75) 48(6.7,-1.25) 49(6.7,-0.75) 50(6.7,-0.25) 51(6.7,0.25) 52(6.7,0.75) 53(6.7,1.25) 54(6.7,1.75) 55(6.7,2.25) 56(6.7,2.75) 57(6.7,3.25) 58(6.7,3.75) 59(6.7,4.25) 60(6.7,4.75)
  oval 0.3x1.5 smd mask+0.05: 21(-4.75,-6.7) 22(-4.25,-6.7) 23(-3.75,-6.7) 24(-3.25,-6.7) 25(-2.75,-6.7) 26(-2.25,-6.7) 27(-1.75,-6.7) 28(-1.25,-6.7) 29(-0.75,-6.7) 30(-0.25,-6.7) 31(0.25,-6.7) 32(0.75,-6.7) 33(1.25,-6.7) 34(1.75,-6.7) 35(2.25,-6.7) 36(2.75,-6.7) 37(3.25,-6.7) 38(3.75,-6.7) 39(4.25,-6.7) 40(4.75,-6.7) 61(4.75,6.7) 62(4.25,6.7) 63(3.75,6.7) 64(3.25,6.7) 65(2.75,6.7) 66(2.25,6.7) 67(1.75,6.7) 68(1.25,6.7) 69(0.75,6.7) 70(0.25,6.7) 71(-0.25,6.7) 72(-0.75,6.7) 73(-1.25,6.7) 74(-1.75,6.7) 75(-2.25,6.7) 76(-2.75,6.7) 77(-3.25,6.7) 78(-3.75,6.7) 79(-4.25,6.7) 80(-4.75,6.7)
  round 1 smd paste-0.5 mask+0.5: 81(-6.7,-6.7) 82(6.7,6.7)
  Top Layer keep-out circle w0.05: c-6.7,-6.7 r1
  Top Layer keep-out circle w0.05: c6.7,6.7 r1
  silkscreen extent -7.32,-5.6 5.6,5.6, body extent -7.01,-7.01 7.01,7.01, height 1.75
QFN-28 [mm]
  rect 0.9x0.3 smd: 1(-2.4,1.5) 2(-2.4,1) 3(-2.4,0.5) 4(-2.4,0) 5(-2.4,-0.5) 6(-2.4,-1) 7(-2.4,-1.5) 15(2.4,-1.5) 16(2.4,-1) 17(2.4,-0.5) 18(2.4,0) 19(2.4,0.5) 20(2.4,1) 21(2.4,1.5)
  rect 0.3x0.9 smd: 8(-1.5,-2.4) 9(-1,-2.4) 10(-0.5,-2.4) 11(0,-2.4) 12(0.5,-2.4) 13(1,-2.4) 14(1.5,-2.4) 22(1.5,2.4) 23(1,2.4) 24(0.5,2.4) 25(0,2.4) 26(-0.5,2.4) 27(-1,2.4) 28(-1.5,2.4)
  silkscreen extent -2.5,-2.5 2.5,2.5
R0603_Pan_ERJ3 [mm] "Resistor, Chip; 1.60 mm L X 0.85 mm W X 0.55 mm H body"
  rrect40% 0.8x1 smd paste-0.025 mask+0.05: 1(-0.775,0) 2(0.775,0)
  silkscreen extent -0.2,-0.48 0.2,0.48, body extent -0.8,-0.43 0.8,0.43, height 0.55
R0603_UniOhm [mm] "Resistor, Chip; 1.60 mm L X 0.825 mm W X 0.55 mm H body"
  rrect40% 0.8x0.95 smd paste-0.025 mask+0.05: 1(-0.75,0) 2(0.75,0)
  silkscreen extent -0.17,-0.48 0.17,0.48, body extent -0.8,-0.41 0.8,0.41, height 0.55
R0603N [mm] "Resistor, Chip, 1.60mm L x 0.80mm W x 0.50mm H"
  rrect10% 0.95x1 smd paste-0.025 mask+0.05: 1(-0.8,0) 2(0.8,0)
  body extent -0.8,-0.4 0.8,0.4, height 0.46
R0805_UniOhm [mm] "Resistor, Chip; 2.00 mm L X 1.275 mm W X 0.65 mm H body"
  rrect40% 0.95x1.4 smd paste-0.025 mask+0.05: 1(-0.9,0) 2(0.9,0)
  silkscreen extent -0.25,-0.7 0.25,0.7, body extent -1,-0.64 1,0.64, height 0.65
R0805_YAGEO [mm] "Resistor, Chip; 2.00 mm L X 1.25 mm W X 0.60 mm H body"
  rrect40% 0.85x1.4 smd paste-0.025 mask+0.05: 1(-0.925,0) 2(0.925,0)
  silkscreen extent -0.32,-0.68 0.32,0.68, body extent -1,-0.63 1,0.63, height 0.6
R0805NH070 [mm] "Resistor, Chip, 2.00mm L x 1.25mm W x 0.70mm H"
  rrect10% 1.05x1.4 smd paste-0.025 mask+0.05: 1(-0.95,0) 2(0.95,0)
  silkscreen extent 0,-0.55 0,0.55, body extent -1,-0.62 1,0.63, height 0.41
R1206NH084 [mm] "Resistor, Chip, 3.20mm L x 1.60mm W x 0.84mm H"
  rrect10% 1.05x1.75 smd paste-0.025 mask+0.05: 1(-1.5,0) 2(1.5,0)
  silkscreen extent -0.6,-0.85 0.6,0.85, body extent -1.6,-0.8 1.6,0.8, height 1
SB_8x8 [mm] "Кнопка 8х8мм"
  rect 1.8x1.8 hole 0.7: 1(-2.5,-3)
  round 1.8 hole 0.7: 2(0,-3) 3(2.5,-3) 4(2.5,3) 5(0,3) 6(-2.5,3)
  silkscreen extent -4,-4.5 4,4.5
SO8_N#1 [mm] "8-Pin Small Outline Integrated Circuit 1.27 mm Pitch, IPC Medium Density"
  oval 2.2x0.6 smd: 1(-2.4,1.905) 2(-2.4,0.635) 3(-2.4,-0.635) 4(-2.4,-1.905) 5(2.4,-1.905) 6(2.4,-0.635) 7(2.4,0.635) 8(2.4,1.905)
  silkscreen extent -2.52,-2.5 0.9,2.88, body extent -1.95,-2.45 1.95,2.45, height 1.75
SO8_N#2 [mm] "8-Pin Small Outline Integrated Circuit 1.27 mm Pitch, IPC Medium Density"
  oval 2.2x0.6 smd: 1(-2.4,1.905) 4(-2.4,-1.905) 5(2.4,-1.905) 8(2.4,1.905)
  oval 2.2x0.55 smd: 2(-2.4,0.635) 3(-2.4,-0.635) 6(2.4,-0.635) 7(2.4,0.635)
  silkscreen extent -2.52,-2.5 0.9,2.88, body extent -1.95,-2.45 1.95,2.45, height 1.75
SO16_N#1 [mm] "SOIC, 16-Leads, Body 9.9x3.9mm, Pitch 1.27mm, IPC Medium Density"
  oval 2.2x0.6 smd: 1(-2.4,4.445) 2(-2.4,3.175) 3(-2.4,1.905) 4(-2.4,0.635) 5(-2.4,-0.635) 6(-2.4,-1.905) 7(-2.4,-3.175) 8(-2.4,-4.445) 9(2.4,-4.445) 10(2.4,-3.175) 11(2.4,-1.905) 12(2.4,-0.635) 13(2.4,0.635) 14(2.4,1.905) 15(2.4,3.175) 16(2.4,4.445)
  silkscreen extent -2.52,-5 0.9,5.42, body extent -1.95,-4.95 1.95,4.95, height 1.75
SO16_N#2 [mm] "SOIC, 16-Leads, Body 9.9x3.9mm, Pitch 1.27mm, IPC Medium Density"
  oval 2.2x0.6 smd: 1(-2.4,4.445) 2(-2.4,3.175) 5(-2.4,-0.635) 6(-2.4,-1.905) 7(-2.4,-3.175) 8(-2.4,-4.445) 9(2.4,-4.445) 10(2.4,-3.175) 11(2.4,-1.905) 12(2.4,-0.635) 13(2.4,0.635) 14(2.4,1.905) 15(2.4,3.175) 16(2.4,4.445)
  oval 2.2x0.55 smd: 3(-2.4,1.905) 4(-2.4,0.635)
  silkscreen extent -2.52,-5 0.9,5.42, body extent -1.95,-4.95 1.95,4.95, height 1.75
SOD80_VISHAY_MINIMELF#1 [mm]
  rrect16% 1.25x2 smd paste-0.025 mask+0.05: A(1.7,0) C(-1.7,0)
  silkscreen extent -2.97,-0.75 0.7,0.75, body extent -1.75,-0.75 1.75,0.75, height 0.75
SOD80_VISHAY_MINIMELF#2 [mm] "Diode, Metal Electrode Leadless Face (MELF); 3.50 mm L X 1.50 mm Dia body"
  rrect40% 1.25x2 smd paste-0.025 mask+0.05: A(1.875,0) C(-1.875,0)
  silkscreen extent -2.68,-0.8 1.07,0.8, body extent -1.85,-0.8 1.85,0.8, height 1.55
SOD323FL_NXP [mm] "SODFL Diode;1.80mm W X 1.35mm L X 0.80mm H body"
  rrect10% 0.85x0.5 smd paste-0.025 mask+0.05: A(1.14,0) C(-1.14,0)
  silkscreen extent -1.7,-0.63 0.85,0.73, body extent -1.35,-0.67 1.35,0.68, height 0.79
SOD323FL_VISHAY_MICROSMP [mm]
  rrect12% 0.8x0.8 smd paste-0.025 mask+0.05: A(1.25,0)
  rrect9% 2x1.1 smd paste-0.05 mask+0.05: C(-0.65,0)
  silkscreen extent -1.98,0.7 -1.78,0.9, body extent -1.15,-0.7 1.15,0.7, height 0.65
SOIC-4N [mm]
  rect 0.9x1.5 smd: 1(-1.3,-2.8) 2(1.3,-2.8) 3(1.3,2.8) 4(-1.3,2.8)
  silkscreen extent -2,-1.9 2,1.9
SOP8_N [mm] "SOIC, 8-Leads, Body 4.9x3.9mm, Pitch 1.27mm, IPC Medium Density"
  oval 2x0.6 smd: 1(-2.5,1.905) 2(-2.5,0.635) 3(-2.5,-0.635) 4(-2.5,-1.905) 5(2.5,-1.905) 6(2.5,-0.635) 7(2.5,0.635) 8(2.5,1.905)
  silkscreen extent -2.62,-2.5 1.1,2.88, body extent -2,-2.5 2,2.5, height 1.75
SOT23-3_DISCRETE [mm] "SOT,0.95mm pitch;3 pin,1.40mm W X 3.04mm L X 1.12mm H body"
  rrect25% 1.05x0.6 smd paste-0.025 mask+0.05: 1(-1.15,0.95) 2(-1.15,-0.95) 3(1.15,0)
  silkscreen extent -1.58,-1.5 0.25,1.92, body extent -1.25,-1.46 1.23,1.46, height 1.02
SOT23_N [mm] "SOT23, 3-Leads, Body 2.9x1.3mm, Pitch 0.95mm, Lead Span 2.3mm, IPC Medium Density"
  rect 1.3x0.6 smd: 1(-1.05,0.95) 2(-1.05,-0.95) 3(1.05,0)
  silkscreen extent -1.18,-1.5 0.7,1.92, body extent -0.7,-1.5 0.7,1.5, height 1.1
SOT323 [mm] "SOT, 0.65mm pitch, 3 pin, 1.25mm W x 2.00mm L x 1.10mm H body"
  rrect50% 0.85x0.55 smd paste-0.025 mask+0.05: 1(-1.05,0.65) 2(-1.05,-0.65) 3(1.05,0)
  silkscreen extent -1.48,-1 0.3,1.4, body extent -1.05,-1 1.05,1, height 0.95
SOT-23-6 [mm]
  rect 0.6x1 smd: 1(0,0) 2(0.95,0) 3(1.9,0) 4(1.9,2.4) 5(0.95,2.4) 6(0,2.4)
  silkscreen extent -0.55,0.4 2.45,2
TQFP48_N [mm] "48-Pin Thin Quad Flat Pack 0.5 mm Pitch, IPC Medium Density"
  oval 1.8x0.3 smd: 1(-4.05,2.75) 2(-4.05,2.25) 3(-4.05,1.75) 4(-4.05,1.25) 5(-4.05,0.75) 6(-4.05,0.25) 7(-4.05,-0.25) 8(-4.05,-0.75) 9(-4.05,-1.25) 10(-4.05,-1.75) 11(-4.05,-2.25) 12(-4.05,-2.75) 25(4.05,-2.75) 26(4.05,-2.25) 27(4.05,-1.75) 28(4.05,-1.25) 29(4.05,-0.75) 30(4.05,-0.25) 31(4.05,0.25) 32(4.05,0.75) 33(4.05,1.25) 34(4.05,1.75) 35(4.05,2.25) 36(4.05,2.75)
  oval 0.3x1.8 smd: 13(-2.75,-4.05) 14(-2.25,-4.05) 15(-1.75,-4.05) 16(-1.25,-4.05) 17(-0.75,-4.05) 18(-0.25,-4.05) 19(0.25,-4.05) 20(0.75,-4.05) 21(1.25,-4.05) 22(1.75,-4.05) 23(2.25,-4.05) 24(2.75,-4.05) 37(2.75,4.05) 38(2.25,4.05) 39(1.75,4.05) 40(1.25,4.05) 41(0.75,4.05) 42(0.25,4.05) 43(-0.25,4.05) 44(-0.75,4.05) 45(-1.25,4.05) 46(-1.75,4.05) 47(-2.25,4.05) 48(-2.75,4.05)
  silkscreen extent -4.17,-2.75 2.75,3.57, body extent -3.5,-3.5 3.5,3.5, height 1.6
TQFP144_N [mm] "Thin QFP, 144-Leads, Body 20x20mm, Pitch 0.5mm, IPC Medium Density"
  oval 1.8x0.3 smd: 1(-10.55,8.75) 2(-10.55,8.25) 3(-10.55,7.75) 4(-10.55,7.25) 5(-10.55,6.75) 6(-10.55,6.25) 7(-10.55,5.75) 8(-10.55,5.25) 9(-10.55,4.75) 10(-10.55,4.25) 11(-10.55,3.75) 12(-10.55,3.25) 13(-10.55,2.75) 14(-10.55,2.25) 15(-10.55,1.75) 16(-10.55,1.25) 17(-10.55,0.75) 18(-10.55,0.25) 19(-10.55,-0.25) 20(-10.55,-0.75) 21(-10.55,-1.25) 22(-10.55,-1.75) 23(-10.55,-2.25) 24(-10.55,-2.75) 25(-10.55,-3.25) 26(-10.55,-3.75) 27(-10.55,-4.25) 28(-10.55,-4.75) 29(-10.55,-5.25) 30(-10.55,-5.75) 31(-10.55,-6.25) 32(-10.55,-6.75) 33(-10.55,-7.25) 34(-10.55,-7.75) 35(-10.55,-8.25) 36(-10.55,-8.75) 73(10.55,-8.75) 74(10.55,-8.25) 75(10.55,-7.75) 76(10.55,-7.25) 77(10.55,-6.75) 78(10.55,-6.25) 79(10.55,-5.75) 80(10.55,-5.25) 81(10.55,-4.75) 82(10.55,-4.25) 83(10.55,-3.75) 84(10.55,-3.25) 85(10.55,-2.75) 86(10.55,-2.25) 87(10.55,-1.75) 88(10.55,-1.25) 89(10.55,-0.75) 90(10.55,-0.25) 91(10.55,0.25) 92(10.55,0.75) 93(10.55,1.25) 94(10.55,1.75) 95(10.55,2.25) 96(10.55,2.75) 97(10.55,3.25) 98(10.55,3.75) 99(10.55,4.25) 100(10.55,4.75) 101(10.55,5.25) 102(10.55,5.75) 103(10.55,6.25) 104(10.55,6.75) 105(10.55,7.25) 106(10.55,7.75) 107(10.55,8.25) 108(10.55,8.75)
  oval 0.3x1.8 smd: 37(-8.75,-10.55) 38(-8.25,-10.55) 39(-7.75,-10.55) 40(-7.25,-10.55) 41(-6.75,-10.55) 42(-6.25,-10.55) 43(-5.75,-10.55) 44(-5.25,-10.55) 45(-4.75,-10.55) 46(-4.25,-10.55) 47(-3.75,-10.55) 48(-3.25,-10.55) 49(-2.75,-10.55) 50(-2.25,-10.55) 51(-1.75,-10.55) 52(-1.25,-10.55) 53(-0.75,-10.55) 54(-0.25,-10.55) 55(0.25,-10.55) 56(0.75,-10.55) 57(1.25,-10.55) 58(1.75,-10.55) 59(2.25,-10.55) 60(2.75,-10.55) 61(3.25,-10.55) 62(3.75,-10.55) 63(4.25,-10.55) 64(4.75,-10.55) 65(5.25,-10.55) 66(5.75,-10.55) 67(6.25,-10.55) 68(6.75,-10.55) 69(7.25,-10.55) 70(7.75,-10.55) 71(8.25,-10.55) 72(8.75,-10.55) 109(8.75,10.55) 110(8.25,10.55) 111(7.75,10.55) 112(7.25,10.55) 113(6.75,10.55) 114(6.25,10.55) 115(5.75,10.55) 116(5.25,10.55) 117(4.75,10.55) 118(4.25,10.55) 119(3.75,10.55) 120(3.25,10.55) 121(2.75,10.55) 122(2.25,10.55) 123(1.75,10.55) 124(1.25,10.55) 125(0.75,10.55) 126(0.25,10.55) 127(-0.25,10.55) 128(-0.75,10.55) 129(-1.25,10.55) 130(-1.75,10.55) 131(-2.25,10.55) 132(-2.75,10.55) 133(-3.25,10.55) 134(-3.75,10.55) 135(-4.25,10.55) 136(-4.75,10.55) 137(-5.25,10.55) 138(-5.75,10.55) 139(-6.25,10.55) 140(-6.75,10.55) 141(-7.25,10.55) 142(-7.75,10.55) 143(-8.25,10.55) 144(-8.75,10.55)
  silkscreen extent -10.67,-9.25 9.25,9.57, body extent -10,-10 10,10, height 1.6
TSOP-44-II [mm]
  rect 0.5x1.2 smd: 1(-8.4,-5.7) 2(-7.6,-5.7) 3(-6.8,-5.7) 4(-6,-5.7) 5(-5.2,-5.7) 6(-4.4,-5.7) 7(-3.6,-5.7) 8(-2.8,-5.7) 9(-2,-5.7) 10(-1.2,-5.7) 11(-0.4,-5.7) 12(0.4,-5.7) 13(1.2,-5.7) 14(2,-5.7) 15(2.8,-5.7) 16(3.6,-5.7) 17(4.4,-5.7) 18(5.2,-5.7) 19(6,-5.7) 20(6.8,-5.7) 21(7.6,-5.7) 22(8.4,-5.7) 23(8.4,5.7) 24(7.6,5.7) 25(6.8,5.7) 26(6,5.7) 27(5.2,5.7) 28(4.4,5.7) 29(3.6,5.7) 30(2.8,5.7) 31(2,5.7) 32(1.2,5.7) 33(0.4,5.7) 34(-0.4,5.7) 35(-1.2,5.7) 36(-2,5.7) 37(-2.8,5.7) 38(-3.6,5.7) 39(-4.4,5.7) 40(-5.2,5.7) 41(-6,5.7) 42(-6.8,5.7) 43(-7.6,5.7) 44(-8.4,5.7)
  silkscreen extent -9.5,-5.1 9.5,5.1
TSSOP16A [mm] "Shrink Small Outline; 16 Leads; Body Width 4.4 mm; Pitch 0.65 mm"
  rect 0.3x1.65 smd: 1(-2.275,-2.775) 2(-1.625,-2.775) 3(-0.975,-2.775) 4(-0.325,-2.775) 5(0.325,-2.775) 6(0.975,-2.775) 7(1.625,-2.775) 8(2.275,-2.775) 9(2.275,2.775) 10(1.625,2.775) 11(0.975,2.775) 12(0.325,2.775) 13(-0.325,2.775) 14(-0.975,2.775) 15(-1.625,2.775) 16(-2.275,2.775)
  silkscreen extent -3.1,-2.9 2.55,1.55
"USB miniB (SMD NNM)" [mm] "USB miniB (Китай)"
  round 0.9 hole 0.9 unplated: 0(-3.145,-3.8) 0(-3.145,0.6)
  rect 2.3x0.5 smd: 1(0,0) 2(0,-0.8) 3(0,-1.6) 4(0,-2.4) 5(0,-3.2)
  Top Layer region: -2.35,-4.95 1.15,-4.95 1.15,-7.55 -2.35,-7.55
  Top Layer region: -7.82,-4.95 -4.32,-4.95 -4.32,-7.55 -7.82,-7.55
  Top Layer region: -2.35,4.35 1.15,4.35 1.15,1.75 -2.35,1.75
  Top Layer region: -7.82,4.35 -4.32,4.35 -4.32,1.75 -7.82,1.75
  Top Layer region: -9.045,1.45 -5.645,1.45 -5.645,-4.65 -9.045,-4.65
  silkscreen extent -9.04,-6.55 0.16,3.35, body extent -9.04,-6.95 0.16,3.75, height 3.95
WSON10 [mm]
  rect 0.25x0.6 smd: 1(-1,-1.4) 2(-0.5,-1.4) 3(0,-1.4) 4(0.5,-1.4) 5(1,-1.4) 6(1,1.4) 7(0.5,1.4) 8(0,1.4) 9(-0.5,1.4) 10(-1,1.4)
  rect 4x1.6 smd: 11(0,0)
  silkscreen extent -1.5,-1.5 1.5,1.5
